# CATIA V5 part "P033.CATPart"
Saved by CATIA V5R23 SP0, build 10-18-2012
Part number: P033
Definition: Axe du galet
Description: Axe du galet
Bounding box of the stored display mesh (mm): x -27 to 27, y -8.5 to 8.5, z -8.496 to 8.453
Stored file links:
  C:\wamp\www\COURS\CONCEPTION GMP1\TITRE 02-SEMESTRE 2\03-TP7-PRESSE MECANIQUE\eleve\P033.CATPart
  \\Gmcao46\Decorse\Catia\presse\Levier\Levier.CATProduct
  C:\Deletré Samuel - GML11\levier_gauche.CATPart
  C:\Deletré Samuel - GML11\levier_droit.CATPart
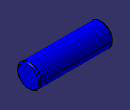
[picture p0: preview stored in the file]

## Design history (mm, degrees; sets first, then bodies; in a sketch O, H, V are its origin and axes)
Set1
  Plane1: type Offset, RefPlane xy-plane, Offset 8.5, reversed
Body1 (main body)
  Sketch1 on yz-plane, origin (0, 0, 0), H (0, 1, 0), V (0, 0, 1)
    circle A1 centre (0, 0) radius 8.5
    radius A1 = 8.5
    concentricity: A1 O
  Pad1: profile Sketch1, direction (1, 0, 0), length 27, mirrored extent
  Chamfer1: length 1, angle 45, on face of Pad1; edge [face of Pad1 | face of Pad1]
  Sketch2 on Plane1, origin (1.016, -0.0417, -8.5), H (1, 0, 0), V (0, 1, 0)
    point P1 (20.984, 0.0417)
    reference intersected line E1 through (-1.016, 0) direction (0, 1) from yz-plane
    reference intersected line E2 through (0, 0.0417) direction (-1, 0) from zx-plane
    distance E1 P1 = 22
    coincidence: E2 P1
  Hole1: placed by Sketch2, at (22, 0, -8.5) direction (0, 0, 1), diameter 4, depth 0.2, V-bottom angle 90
